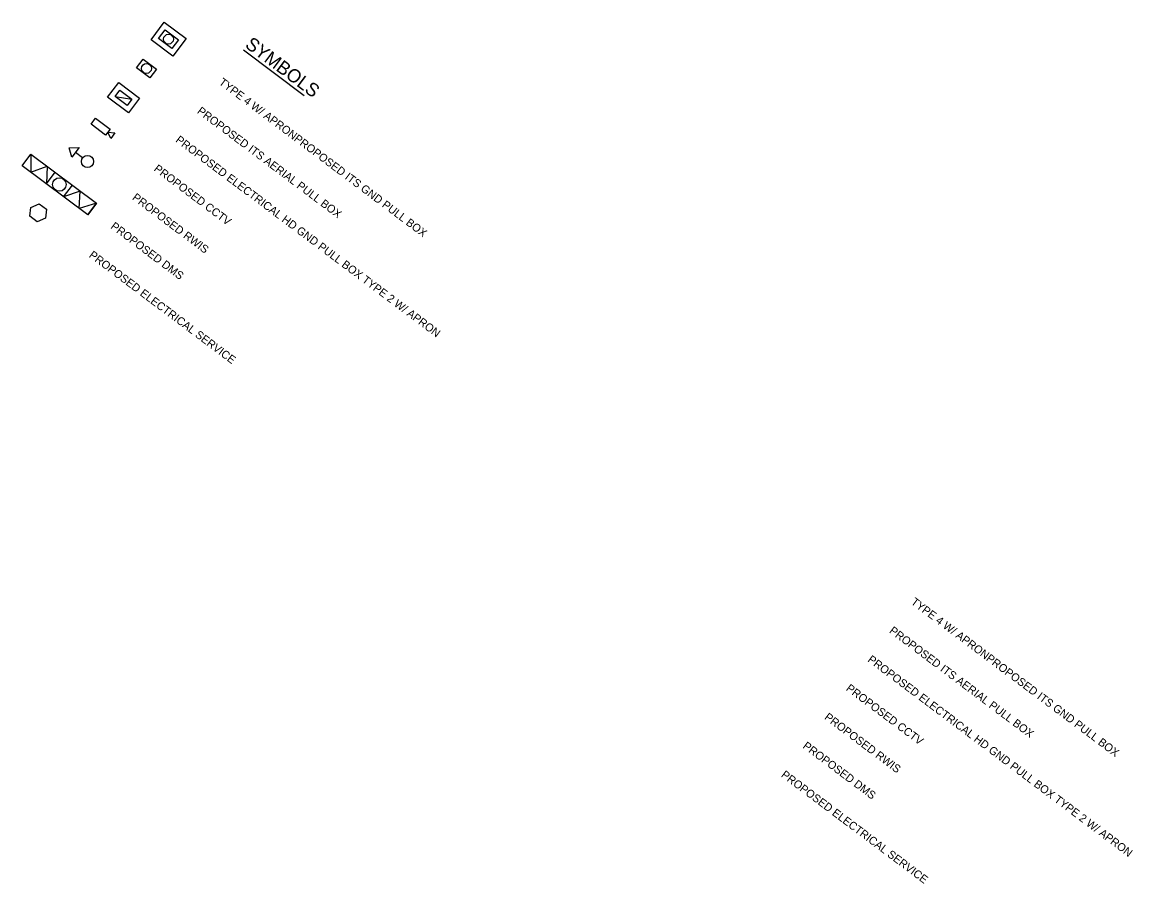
# Model space of a CAD drawing. Extents: x 626494 to 628870, y 365986 to 369334.
# Drawn here: x 628370.2 to 628869.5, y 368161.9 to 368549.4 of the extents above; entities that cross this region are included whole.
import ezdxf

# ---------------------------------------------------------------- set-up
doc = ezdxf.new("R2010")
doc.units = 0
doc.layers.add('R_Grid_SCR50', color=7, linetype='Continuous')
doc.layers.add('R_Shade Frontage Road', color=7, linetype='Continuous')

msp = doc.modelspace()

# ---------------------------------------------------------------- linework, layer by layer
at = {"layer": 'R_Grid_SCR50'}
for p, q in [((628397.31, 368488.37), (628394.08, 368490.8)), ((628374.07, 368466.13), (628377.81, 368467.73)), ((628377.81, 368467.73), (628381.05, 368465.29)), ((628373.59, 368462.1), (628374.07, 368466.13)), ((628376.84, 368459.67), (628373.59, 368462.1)), ((628381.05, 368465.29), (628380.58, 368461.27)), ((628380.58, 368461.27), (628376.84, 368459.67))]:
    msp.add_line(p, q, dxfattribs=at)
for points in [[(628433.98, 368549.39), (628443.81, 368542), (628437.9, 368534.13), (628428.07, 368541.52)], [(628434.47, 368545.94), (628440.37, 368541.51), (628437.41, 368537.58), (628431.51, 368542.01)], [(628424.57, 368532.76), (628430.47, 368528.33), (628427.52, 368524.4), (628421.61, 368528.83)], [(628413.54, 368522.23), (628422.88, 368515.21), (628417.92, 368508.61), (628408.58, 368515.62)], [(628414.07, 368518.88), (628419.52, 368514.79), (628417.38, 368511.93), (628411.92, 368516.03)], [(628411.94, 368516.05), (628419.52, 368514.79), (628417.38, 368511.93)], [(628403.12, 368506.24), (628409.69, 368501.31), (628407.68, 368498.62), (628401.11, 368503.56)], [(628408.69, 368499.96), (628411.87, 368499.66), (628409.99, 368497.16)], [(628395.72, 368492.98), (628392.44, 368488.62), (628391.24, 368492.92)]]:
    msp.add_lwpolyline(points, close=True, dxfattribs=at)
for points in [[(628370.16, 368484.85), (628374.1, 368490.1), (628374.01, 368481.96), (628381.43, 368484.59), (628381.03, 368476.69), (628384.97, 368481.93)], [(628399.63, 368462.72), (628403.57, 368467.96), (628395.78, 368465.61), (628396.24, 368473.47), (628388.76, 368470.88), (628392.7, 368476.13)]]:
    msp.add_lwpolyline(points, dxfattribs=at)
for centre, radius in [((628435.94, 368541.76), 2.21), ((628426.04, 368528.58), 2.21), ((628399.49, 368486.72), 2.73), ((628386.86, 368476.4), 3.06)]:
    msp.add_circle(centre, radius, dxfattribs=at)
at = {"layer": 'R_Shade Frontage Road'}
msp.add_line((628469.58, 368537.02), (628496.93, 368516.48), dxfattribs=at)
msp.add_lwpolyline([(628374.1, 368490.1), (628403.57, 368467.96), (628399.63, 368462.72), (628370.16, 368484.85)], close=True, dxfattribs=at)

# ---------------------------------------------------------------- texts
for s, height, p in [('SYMBOLS', 6, (628469.95, 368538.42)), ('TYPE 4 W/ APRONPROPOSED ITS GND PULL BOX', 3.6, (628458.26, 368521.72)), ('PROPOSED ITS AERIAL PULL BOX', 3.6, (628448.53, 368508.76)), ('PROPOSED ELECTRICAL HD GND PULL BOX TYPE 2 W/ APRON', 3.6, (628438.8, 368495.81)), ('PROPOSED CCTV', 3.6, (628429.07, 368482.85)), ('PROPOSED RWIS', 3.6, (628419.35, 368469.9)), ('PROPOSED DMS', 3.6, (628409.62, 368456.95)), ('PROPOSED ELECTRICAL SERVICE', 3.6, (628399.89, 368443.99)), ('TYPE 4 W/ APRONPROPOSED ITS GND PULL BOX', 3.6, (628769.46, 368288.03)), ('PROPOSED ITS AERIAL PULL BOX', 3.6, (628759.73, 368275.08)), ('PROPOSED ELECTRICAL HD GND PULL BOX TYPE 2 W/ APRON', 3.6, (628750, 368262.12)), ('PROPOSED CCTV', 3.6, (628740.28, 368249.17)), ('PROPOSED RWIS', 3.6, (628730.55, 368236.22)), ('PROPOSED DMS', 3.6, (628720.82, 368223.26)), ('PROPOSED ELECTRICAL SERVICE', 3.6, (628711.09, 368210.31))]:
    msp.add_text(s, height=height, rotation=323.0968, dxfattribs=at).set_placement(p)

doc.saveas('drawing.dxf')
